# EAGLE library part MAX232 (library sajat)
RS232 TRANSEIVER
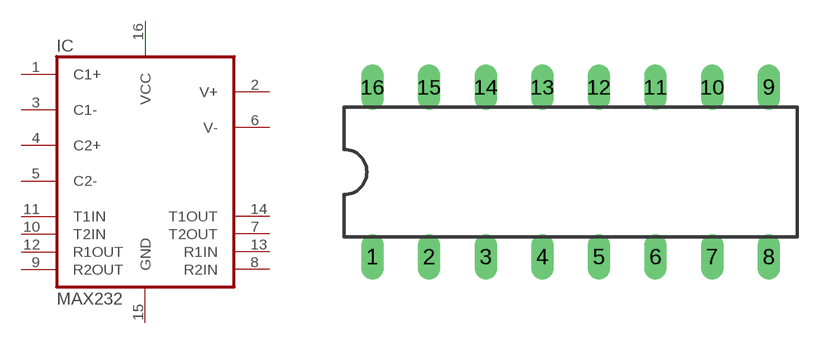
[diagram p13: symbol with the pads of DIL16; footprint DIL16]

Designator prefix IC

## MAX232  [DIL16]
1  C1+
2  V+
3  C1-
4  C2+
5  C2-
6  V-
7  T2OUT  out
8  R2IN  in
9  R2OUT  out
10  T2IN  in
11  T1IN  in
12  R1OUT  out
13  R1IN  in
14  T1OUT  out
15  GND
16  VCC

## Footprint DIL16 (pad centres in mm)
Dual In Line Package
drill 0.3 pad 1.016 long: 1 -8.89,-3.81; 2 -6.35,-3.81; 3 -3.81,-3.81; 4 -1.27,-3.81; 5 1.27,-3.81; 6 3.81,-3.81; 7 6.35,-3.81; 8 8.89,-3.81; 9 8.89,3.81; 10 6.35,3.81; 11 3.81,3.81; 12 1.27,3.81; 13 -1.27,3.81; 14 -3.81,3.81; 15 -6.35,3.81; 16 -8.89,3.81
